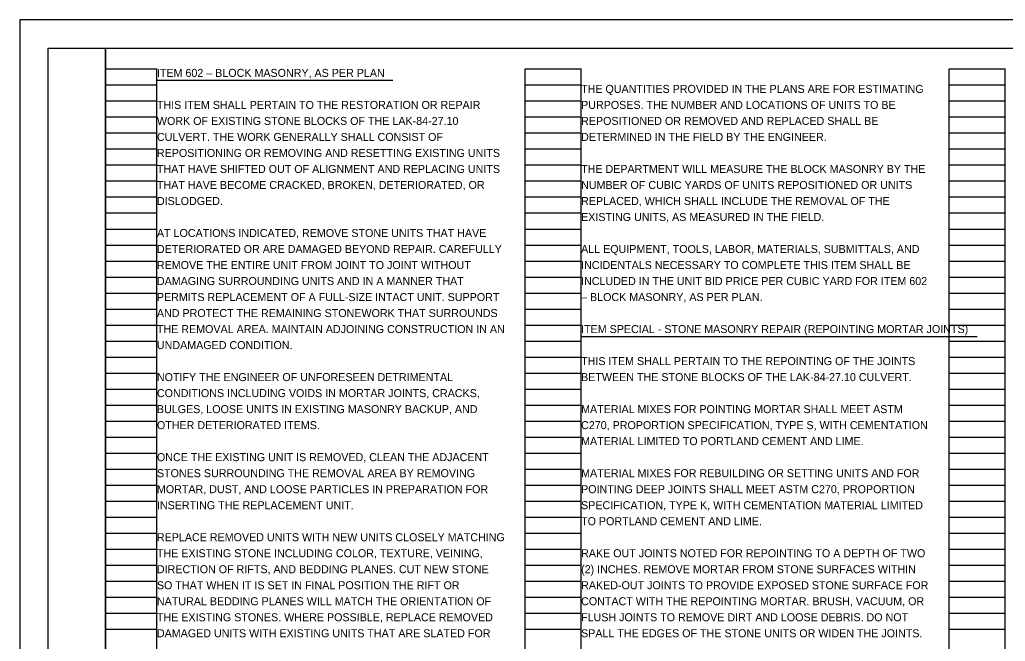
# Model space of a CAD drawing. Extents: x 0 to 34, y 0 to 22.
# Drawn here: x 0 to 17.24, y 11.13 to 22 of the extents above; entities that cross this region are included whole.
import ezdxf

# ---------------------------------------------------------------- set-up
doc = ezdxf.new("R2010")
doc.units = 0
for name, color, linetype in [('SH_Border', 7, 'Continuous'), ('SH_Cut_Line', 7, 'Continuous'), ('SH_Data', 7, 'Continuous'), ('SH_Text', 7, 'Continuous')]:
    doc.layers.add(name, color=color, linetype=linetype)

msp = doc.modelspace()

# ---------------------------------------------------------------- linework, layer by layer
at = {"layer": 'SH_Border'}
for points in [[(0.5, 21.5), (1.5, 21.5), (1.5, 0.5), (0.5, 0.5)], [(1.5, 21.5), (33.5, 21.5), (33.5, 0.5), (1.5, 0.5)]]:
    msp.add_lwpolyline(points, close=True, dxfattribs=at)
at = {"layer": 'SH_Cut_Line'}
msp.add_lwpolyline([(0, 0), (34, 0), (34, 22), (0, 22)], close=True, dxfattribs=at)
at = {"layer": 'SH_Data'}
for p, q in [((1.5, 0.98), (1.5, 21.14)), ((1.5, 21.14), (2.4, 21.14)), ((2.4, 0.98), (2.4, 21.14)), ((8.84, 0.98), (8.84, 21.14)), ((8.84, 21.14), (9.82, 21.14)), ((9.82, 0.98), (9.82, 21.14)), ((16.26, 0.98), (16.26, 21.14)), ((16.26, 21.14), (17.24, 21.14)), ((17.24, 0.98), (17.24, 21.14)), ((1.5, 20.86), (2.4, 20.86)), ((8.84, 20.86), (9.82, 20.86)), ((16.26, 20.86), (17.24, 20.86)), ((1.5, 20.58), (2.4, 20.58)), ((8.84, 20.58), (9.82, 20.58)), ((16.26, 20.58), (17.24, 20.58)), ((1.5, 20.3), (2.4, 20.3)), ((8.84, 20.3), (9.82, 20.3)), ((16.26, 20.3), (17.24, 20.3)), ((1.5, 20.02), (2.4, 20.02)), ((8.84, 20.02), (9.82, 20.02)), ((16.26, 20.02), (17.24, 20.02)), ((1.5, 19.74), (2.4, 19.74)), ((8.84, 19.74), (9.82, 19.74)), ((16.26, 19.74), (17.24, 19.74)), ((1.5, 19.46), (2.4, 19.46)), ((8.84, 19.46), (9.82, 19.46)), ((16.26, 19.46), (17.24, 19.46)), ((1.5, 19.18), (2.4, 19.18)), ((8.84, 19.18), (9.82, 19.18)), ((16.26, 19.18), (17.24, 19.18)), ((1.5, 18.9), (2.4, 18.9)), ((8.84, 18.9), (9.82, 18.9)), ((16.26, 18.9), (17.24, 18.9)), ((1.5, 18.62), (2.4, 18.62)), ((8.84, 18.62), (9.82, 18.62)), ((16.26, 18.62), (17.24, 18.62)), ((1.5, 18.34), (2.4, 18.34)), ((8.84, 18.34), (9.82, 18.34)), ((16.26, 18.34), (17.24, 18.34)), ((1.5, 18.06), (2.4, 18.06)), ((8.84, 18.06), (9.82, 18.06)), ((16.26, 18.06), (17.24, 18.06)), ((1.5, 17.78), (2.4, 17.78)), ((8.84, 17.78), (9.82, 17.78)), ((16.26, 17.78), (17.24, 17.78)), ((1.5, 17.5), (2.4, 17.5)), ((8.84, 17.5), (9.82, 17.5)), ((16.26, 17.5), (17.24, 17.5)), ((1.5, 17.22), (2.4, 17.22)), ((8.84, 17.22), (9.82, 17.22)), ((16.26, 17.22), (17.24, 17.22)), ((1.5, 16.94), (2.4, 16.94)), ((8.84, 16.94), (9.82, 16.94)), ((16.26, 16.94), (17.24, 16.94)), ((1.5, 16.66), (2.4, 16.66)), ((8.84, 16.66), (9.82, 16.66)), ((16.26, 16.66), (17.24, 16.66)), ((1.5, 16.38), (2.4, 16.38)), ((8.84, 16.38), (9.82, 16.38)), ((16.26, 16.38), (17.24, 16.38)), ((1.5, 16.1), (2.4, 16.1)), ((8.84, 16.1), (9.82, 16.1)), ((16.26, 16.1), (17.24, 16.1)), ((1.5, 15.82), (2.4, 15.82)), ((8.84, 15.82), (9.82, 15.82)), ((16.26, 15.82), (17.24, 15.82)), ((1.5, 15.54), (2.4, 15.54)), ((8.84, 15.54), (9.82, 15.54)), ((16.26, 15.54), (17.24, 15.54)), ((1.5, 15.26), (2.4, 15.26)), ((8.84, 15.26), (9.82, 15.26)), ((16.26, 15.26), (17.24, 15.26)), ((1.5, 14.98), (2.4, 14.98)), ((8.84, 14.98), (9.82, 14.98)), ((16.26, 14.98), (17.24, 14.98)), ((1.5, 14.7), (2.4, 14.7)), ((8.84, 14.7), (9.82, 14.7)), ((16.26, 14.7), (17.24, 14.7)), ((1.5, 14.42), (2.4, 14.42)), ((8.84, 14.42), (9.82, 14.42)), ((16.26, 14.42), (17.24, 14.42)), ((1.5, 14.14), (2.4, 14.14)), ((8.84, 14.14), (9.82, 14.14)), ((16.26, 14.14), (17.24, 14.14)), ((1.5, 13.86), (2.4, 13.86)), ((8.84, 13.86), (9.82, 13.86)), ((16.26, 13.86), (17.24, 13.86)), ((1.5, 13.58), (2.4, 13.58)), ((8.84, 13.58), (9.82, 13.58)), ((16.26, 13.58), (17.24, 13.58)), ((1.5, 13.3), (2.4, 13.3)), ((8.84, 13.3), (9.82, 13.3)), ((16.26, 13.3), (17.24, 13.3)), ((1.5, 13.02), (2.4, 13.02)), ((8.84, 13.02), (9.82, 13.02)), ((16.26, 13.02), (17.24, 13.02)), ((1.5, 12.74), (2.4, 12.74)), ((8.84, 12.74), (9.82, 12.74)), ((16.26, 12.74), (17.24, 12.74)), ((1.5, 12.46), (2.4, 12.46)), ((8.84, 12.46), (9.82, 12.46)), ((16.26, 12.46), (17.24, 12.46)), ((1.5, 12.18), (2.4, 12.18)), ((8.84, 12.18), (9.82, 12.18)), ((16.26, 12.18), (17.24, 12.18)), ((1.5, 11.9), (2.4, 11.9)), ((8.84, 11.9), (9.82, 11.9)), ((16.26, 11.9), (17.24, 11.9)), ((1.5, 11.62), (2.4, 11.62)), ((8.84, 11.62), (9.82, 11.62)), ((16.26, 11.62), (17.24, 11.62)), ((1.5, 11.34), (2.4, 11.34)), ((8.84, 11.34), (9.82, 11.34)), ((16.26, 11.34), (17.24, 11.34))]:
    msp.add_line(p, q, dxfattribs=at)
at = {"layer": 'SH_Text'}
for p, q in [((2.412, 20.942), (6.528, 20.942)), ((9.832, 16.462), (16.75, 16.462))]:
    msp.add_line(p, q, dxfattribs=at)

# ---------------------------------------------------------------- texts
for s, p in [('ITEM 602 – BLOCK MASONRY, AS PER PLAN', (2.4, 21)), ('THE QUANTITIES PROVIDED IN THE PLANS ARE FOR ESTIMATING ', (9.82, 20.72)), ('THIS ITEM SHALL PERTAIN TO THE RESTORATION OR REPAIR ', (2.4, 20.44)), ('PURPOSES. THE NUMBER AND LOCATIONS OF UNITS TO BE ', (9.82, 20.44)), ('WORK OF EXISTING STONE BLOCKS OF THE LAK-84-27.10 ', (2.4, 20.16)), ('REPOSITIONED OR REMOVED AND REPLACED SHALL BE ', (9.82, 20.16)), ('CULVERT. THE WORK GENERALLY SHALL CONSIST OF ', (2.4, 19.88)), ('DETERMINED IN THE FIELD BY THE ENGINEER.', (9.82, 19.88)), ('REPOSITIONING OR REMOVING AND RESETTING EXISTING UNITS ', (2.4, 19.6)), ('THAT HAVE SHIFTED OUT OF ALIGNMENT AND REPLACING UNITS ', (2.4, 19.32)), ('THE DEPARTMENT WILL MEASURE THE BLOCK MASONRY BY THE ', (9.82, 19.32)), ('THAT HAVE BECOME CRACKED, BROKEN, DETERIORATED, OR ', (2.4, 19.04)), ('NUMBER OF CUBIC YARDS OF UNITS REPOSITIONED OR UNITS ', (9.82, 19.04)), ('DISLODGED.', (2.4, 18.76)), ('REPLACED, WHICH SHALL INCLUDE THE REMOVAL OF THE ', (9.82, 18.76)), ('EXISTING UNITS, AS MEASURED IN THE FIELD.', (9.82, 18.48)), ('AT LOCATIONS INDICATED, REMOVE STONE UNITS THAT HAVE ', (2.4, 18.2)), ('DETERIORATED OR ARE DAMAGED BEYOND REPAIR. CAREFULLY ', (2.4, 17.92)), ('ALL EQUIPMENT, TOOLS, LABOR, MATERIALS, SUBMITTALS, AND ', (9.82, 17.92)), ('REMOVE THE ENTIRE UNIT FROM JOINT TO JOINT WITHOUT ', (2.4, 17.64)), ('INCIDENTALS NECESSARY TO COMPLETE THIS ITEM SHALL BE ', (9.82, 17.64)), ('DAMAGING SURROUNDING UNITS AND IN A MANNER THAT ', (2.4, 17.36)), ('INCLUDED IN THE UNIT BID PRICE PER CUBIC YARD FOR ITEM 602 ', (9.82, 17.36)), ('PERMITS REPLACEMENT OF A FULL-SIZE INTACT UNIT. SUPPORT ', (2.4, 17.08)), ('– BLOCK MASONRY, AS PER PLAN.', (9.82, 17.08)), ('AND PROTECT THE REMAINING STONEWORK THAT SURROUNDS ', (2.4, 16.8)), ('THE REMOVAL AREA. MAINTAIN ADJOINING CONSTRUCTION IN AN ', (2.4, 16.52)), ('ITEM SPECIAL - STONE MASONRY REPAIR (REPOINTING MORTAR JOINTS)', (9.82, 16.52)), ('UNDAMAGED CONDITION.  ', (2.4, 16.24)), ('THIS ITEM SHALL PERTAIN TO THE REPOINTING OF THE JOINTS ', (9.82, 15.96)), ('NOTIFY THE ENGINEER OF UNFORESEEN DETRIMENTAL ', (2.4, 15.68)), ('BETWEEN THE STONE BLOCKS OF THE LAK-84-27.10 CULVERT.', (9.82, 15.68)), ('CONDITIONS INCLUDING VOIDS IN MORTAR JOINTS, CRACKS, ', (2.4, 15.4)), ('BULGES, LOOSE UNITS IN EXISTING MASONRY BACKUP, AND ', (2.4, 15.12)), ('MATERIAL MIXES FOR POINTING MORTAR SHALL MEET ASTM ', (9.82, 15.12)), ('OTHER DETERIORATED ITEMS.', (2.4, 14.84)), ('C270, PROPORTION SPECIFICATION, TYPE S, WITH CEMENTATION ', (9.82, 14.84)), ('MATERIAL LIMITED TO PORTLAND CEMENT AND LIME. ', (9.82, 14.56)), ('ONCE THE EXISTING UNIT IS REMOVED, CLEAN THE ADJACENT ', (2.4, 14.28)), ('STONES SURROUNDING THE REMOVAL AREA BY REMOVING ', (2.4, 14)), ('MATERIAL MIXES FOR REBUILDING OR SETTING UNITS AND FOR ', (9.82, 14)), ('MORTAR, DUST, AND LOOSE PARTICLES IN PREPARATION FOR ', (2.4, 13.72)), ('POINTING DEEP JOINTS SHALL MEET ASTM C270, PROPORTION ', (9.82, 13.72)), ('INSERTING THE REPLACEMENT UNIT.', (2.4, 13.44)), ('SPECIFICATION, TYPE K, WITH CEMENTATION MATERIAL LIMITED ', (9.82, 13.44)), ('TO PORTLAND CEMENT AND LIME. ', (9.82, 13.16)), ('REPLACE REMOVED UNITS WITH NEW UNITS CLOSELY MATCHING ', (2.4, 12.88)), ('THE EXISTING STONE INCLUDING COLOR, TEXTURE, VEINING, ', (2.4, 12.6)), ('RAKE OUT JOINTS NOTED FOR REPOINTING TO A DEPTH OF TWO ', (9.82, 12.6)), ('DIRECTION OF RIFTS, AND BEDDING PLANES. CUT NEW STONE ', (2.4, 12.32)), ('(2) INCHES. REMOVE MORTAR FROM STONE SURFACES WITHIN ', (9.82, 12.32)), ('SO THAT WHEN IT IS SET IN FINAL POSITION THE RIFT OR ', (2.4, 12.04)), ('RAKED-OUT JOINTS TO PROVIDE EXPOSED STONE SURFACE FOR ', (9.82, 12.04)), ('NATURAL BEDDING PLANES WILL MATCH THE ORIENTATION OF ', (2.4, 11.76)), ('CONTACT WITH THE REPOINTING MORTAR. BRUSH, VACUUM, OR ', (9.82, 11.76)), ('THE EXISTING STONES. WHERE POSSIBLE, REPLACE REMOVED ', (2.4, 11.48)), ('FLUSH JOINTS TO REMOVE DIRT AND LOOSE DEBRIS. DO NOT ', (9.82, 11.48)), ('DAMAGED UNITS WITH EXISTING UNITS THAT ARE SLATED FOR ', (2.4, 11.2)), ('SPALL THE EDGES OF THE STONE UNITS OR WIDEN THE JOINTS. ', (9.82, 11.2))]:
    msp.add_text(s, height=0.14, rotation=360, dxfattribs=at).set_placement(p)

doc.saveas('drawing.dxf')
